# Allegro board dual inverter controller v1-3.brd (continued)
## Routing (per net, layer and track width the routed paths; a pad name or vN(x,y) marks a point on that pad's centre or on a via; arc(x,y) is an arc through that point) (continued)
Z-RTD-N-FILTER: length 5.4
  TOP w0.381: RT214.2 71.53,16.71 72.74,17.92 UT34.7
  TOP w0.508: RT214.2 CT142.2 70,16.62 LT23.2
Z-RTD-P: length 38.4
  TOP w0.381: JB6.9 34.42,8.62 37.03,11.23 54.06,11.23 61.11,18.27 66.78,18.27 LT20.1
Z-RTD-P-FILTER: length 5
  TOP w0.381: RT214.1 71.9,18.31 72.16,18.57 UT34.6
  TOP w0.508: RT214.1 CT142.1 70,18.4 LT20.2
Z-TEMP: length 22
  TOP w0.381: v1(101.64,44.39) 101.62,44.41 JT26.39
  BOTTOM w0.381: v1(101.64,44.39) 101.64,45.02 102.74,46.11 102.74,53.55 102.39,53.9 102.39,55.38 100.86,56.9 CB53.1 RB71.2
ZHS-PWM: length 46
  TOP w0.381: JT26.61 113.64,44.09 110.43,40.88 v1(104.91,40.88) 89.42,40.88 88.78,40.24 84.21,40.24 83.02,39.05 JT32.1
  TOP w0.508: RT165.1 77.98,34.09 80.71,36.81 JT32.1
ZHS-PWM-N: length 60.9
  TOP w0.381: JB6.4 28.06,5.49 28.06,11.75 30.36,14.04 51.18,14.04 66.54,29.4 71.12,29.4 71.64,29.92 73.27,29.92 UT26.3
ZHS-PWM-P: length 59
  TOP w0.381: JB6.3 26.8,11.28 30.12,14.6 50.95,14.6 66.3,29.95 70.89,29.95 71.41,30.48 73.3,30.48 UT26.2
ZLS-PWM: length 53.3
  TOP w0.381: JT26.63 114.43,43.76 110.76,40.09 v1(104.91,40.09) 89.74,40.09 89.12,39.46 JT33.1
  TOP w0.508: RT195.1 75.53,23.68 77.1,25.26 80.66,25.26 89.12,33.72 JT33.1
ZLS-PWM-N: length 58.6
  TOP w0.381: v1(29.22,10.02) 32.66,13.46 52.22,13.46 67.23,28.47 72.48,28.47 72.51,28.5 73.27,28.5 UT26.5
  BOTTOM w0.381: v1(29.22,10.02) 28.09,8.88 28.09,5.49 JB6.6
ZLS-PWM-P: length 54.3
  TOP w0.381: UT26.6 73.3,27.94 72.74,27.94 72.71,27.91 67.46,27.91 52.45,12.9 32.9,12.9 29.89,9.9 29.89,9.74 29.78,9.62 29.78,9.38 29.34,8.95 JB6.5
N07282: length 3.2
  TOP w0.381: UT8.4 98.74,115.56 v1(98.56,115.38)
  BOTTOM w0.381: v1(98.56,115.38) 98.56,114.29 RB13.2
N07299: length 3.6
  TOP w0.381: UT8.12 96.6,116.21 v1(96.78,116.39)
  BOTTOM w0.381: v1(96.78,116.39) 96.78,117.77 RB5.1
N07508: length 3.2
  TOP w0.381: v1(76.18,116.57) 75.87,116.26 UT4.4
  BOTTOM w0.381: v1(76.18,116.57) 76.18,117.54 RB6.2
N07516: length 3.3
  TOP w0.381: v1(78.22,115.43) 78.4,115.61 UT4.12
  BOTTOM w0.381: RB14.1 77.93,115.14 v1(78.22,115.43)
N07693: length 3.2
  TOP w0.381: UT1.4 v1(98.77,125.77)
  BOTTOM w0.381: RB3.2 98.77,124.71 v1(98.77,125.77)
N07878: length 3.2
  TOP w0.381: UT2.4 76.05,126.29 v1(76.24,126.47)
  BOTTOM w0.381: RB2.2 76.24,127.66 v1(76.24,126.47)
N09835: length 3.4
  TOP w0.381: UT1.1 102.25,123.82 CT6.1 RT20.2
N10049: length 3.7
  TOP w0.381: RT3.2 CT4.1 101.51,127.72 UT1.7
N10085: length 3.5
  TOP w0.381: RT2.2 CT3.1 93.23,128.37 UT1.9
N10121: length 3.5
  TOP w0.381: UT1.15 93.37,124.47 CT5.1 RT13.2
N11382: length 3.5
  TOP w0.381: UT1.12 v1(96.88,126.42)
  BOTTOM w0.381: RB1.2 96.88,127.73 v1(96.88,126.42)
N11987: length 3.3
  TOP w0.381: UT2.12 78.32,125.64 v1(78.14,125.46)
  BOTTOM w0.381: RB4.2 78.14,124.28 v1(78.14,125.46)
N12714: length 3
  TOP w0.381: RT1.2 CT1.1 74.17,128.48 UT2.1
N12754: length 5.8
  TOP w0.381: RT28.2 CT14.1 73.37,122.28 72.93,122.72 72.93,123.99 73.28,124.34 UT2.7
N16187: length 25
  LAYER3 w0.381: v1(84.96,65.03) 84.96,80.08 v1(83.73,81.31)
  BOTTOM w0.381: CB24.2 v1(83.73,81.31) ; RB66.1 84.59,64.66 v1(84.96,65.03)
  BOTTOM w0.508: UB6.1 80.28,83.89 81.38,82.78 81.61,82.78 82.18,82.21 UB6.4 82.97,82.78 CB24.2
N16636: length 2.8
  BOTTOM w0.508: CB24.1 RB38.1 RB35.2
N16643: length 3.3
  BOTTOM w0.508: RB38.2 83.67,84.15 82.81,84.15 82.27,84.69 UB6.3 82.41,84.92 CB18.2
N18013: length 2.8
  BOTTOM w0.508: CB25.1 RB39.1 RB36.2
N18021: length 26.1
  LAYER3 w0.381: v1(89.47,64.96) 93.46,68.94 v1(93.46,80.86)
  BOTTOM w0.381: v1(93.46,80.86) 93.46,81.5 92.97,81.99 UB7.4 ; RB67.1 v1(89.47,64.96)
  BOTTOM w0.508: UB7.1 90.45,83.89 91.56,82.78 91.78,82.78 92.35,82.21 UB7.4 93.15,82.78 CB25.2
N18093: length 3.3
  BOTTOM w0.508: CB19.2 92.58,84.92 UB7.3 92.45,84.69 92.99,84.15 93.85,84.15 RB39.2
N18488: length 2.8
  BOTTOM w0.508: RB37.2 RB40.1 CB26.1
N18496: length 29.8
  LAYER3 w0.381: v1(91.1,64.96) 97.08,70.94 97.08,73.13 97.04,73.17 97.04,77.53 99.35,79.84 101.74,79.84 v1(102.42,80.53)
  BOTTOM w0.381: RB68.1 v1(91.1,64.96) ; UB8.4 102.42,81.88 v1(102.42,80.53)
  BOTTOM w0.508: CB26.2 103.32,82.78 UB8.4 102.53,82.21 101.96,82.78 101.73,82.78 100.63,83.89 UB8.1
N18568: length 3.3
  BOTTOM w0.508: CB20.2 102.76,84.92 UB8.3 102.62,84.69 103.16,84.15 104.02,84.15 RB40.2
N76078: length 10
  TOP w0.381: RT27.2 45.03,121.52 RT29.1
  TOP w0.508: CT15.2 RT27.2
  TOP w0.635: RT12.2 40.9,120.77 41.64,120.02 RT29.1
N76134: length 2
  TOP w0.508: UT3.3 46.36,120.02 RT29.2
N76224: length 67.8
  TOP w0.381: UT3.1 51.75,119.44 v1(52.72,118.47)
  TOP w0.508: UT3.1 48.84,118.41 48.48,118.05 46.54,118.05 45.86,118.73 CT17.2 RT36.2
  BOTTOM w0.381: RB65.1 64.7,105.47 52.72,117.46 v1(52.72,118.47)
N76236: length 2.3
  TOP w0.508: RT43.2 46.36,115.93 46.94,116.52 UT3.4
N76260: length 5.5
  TOP w0.508: CT17.1 RT36.1 RT43.1
  TOP w0.635: RT42.2 42.38,116.19 42.64,115.93 RT43.1
N78650: length 2.8
  BOTTOM w0.508: RB25.2 RB18.1 CB7.1
N78658: length 9.6
  BOTTOM w0.381: RB26.1 75.52,95.99 76.53,97 76.53,97.85 76.09,98.28 75.88,98.28 75.35,98.81 UB2.1
  BOTTOM w0.508: UB2.1 75.35,99.83 74.25,100.94 74.02,100.94 73.45,101.51 UB2.4 72.66,100.94 CB7.2
N78724: length 3.3
  BOTTOM w0.508: RB18.2 71.96,99.57 72.82,99.57 73.36,99.03 UB2.3 73.22,98.8 CB9.2
N79088: length 5.9
  BOTTOM w0.381: RB28.2 72.33,96.76 71.9,97.19 RB25.1 ; RB28.2 CB10.2 ; RB28.2 70.99,95.99 RB27.1
N88263: length 1.6
  TOP w0.381: RT192.2 DT7.1
N88433: length 1.6
  TOP w0.381: RT193.2 DT8.1
N93191: length 1.9
  TOP w0.381: DT4.1 RT152.2
N93195: length 1.9
  TOP w0.381: DT6.1 RT154.2
N93199: length 1.9
  TOP w0.381: DT5.1 RT153.2
N139937: length 1.8
  TOP w0.635: RT10.2 RT11.1
N139941: length 1.8
  TOP w0.635: RT11.2 RT12.1
N140053: length 1.8
  TOP w0.635: RT40.2 RT41.1
N140057: length 1.8
  TOP w0.635: RT41.2 RT42.1
N147166: length 30.2
  TOP w0.381: 222.02,13.15 QT2.2 ; QT2.2 223.04,14.2 ; QT2.2 222.02,14.2 ; QT2.2 222.53,13.15 ; QT2.2 223.05,13.67 ; QT2.2 222.53,14.2 ; QT2.2 222.01,13.67 ; QT2.2 223.04,13.15 ; 222.02,14.42 QT2.3 ; QT2.3 223.04,14.42 ; QT2.3 222.01,14.94 ; QT2.3 223.05,14.94 ; QT2.3 223.04,15.47 ; QT2.3 222.02,15.47 ; QT2.3 222.53,14.42 ; QT2.3 222.53,15.47 ; QT3.3 225.57,14.2 ; QT3.3 225.57,13.15 ; QT3.3 225.06,13.15 ; QT3.3 224.55,13.15 ; QT3.3 224.55,14.2 ; QT3.3 225.58,13.67 ; QT3.3 224.54,13.67 ; QT3.3 225.06,14.2 ; QT2.1 223.04,12.93 ; QT2.1 222.02,11.88 ; QT2.1 223.05,12.4 ; QT2.1 222.53,12.93 ; QT2.1 222.02,12.93 ; QT2.1 223.04,11.88 ; QT2.1 222.01,12.4 ; QT2.1 222.53,11.88 ; QT3.2 225.58,14.94 ; QT3.2 224.54,14.94 ; QT3.2 225.57,14.42 ; QT3.2 225.06,14.42 ; QT3.2 224.55,15.47 ; QT3.2 224.55,14.42 ; QT3.2 225.06,15.47 ; QT3.2 225.57,15.47 ; 224.55,15.69 QT3.1 ; QT3.1 225.06,16.74 ; QT3.1 225.58,16.21 ; QT3.1 225.57,15.69 ; QT3.1 225.06,15.69 ; QT3.1 225.57,16.74 ; QT3.1 224.54,16.21 ; QT3.1 224.55,16.74
N148075: length 18.1
  TOP w0.254: v1(223.44,7.69) 222.23,7.69 UT37.10 221.85,7.7 221.52,7.37 221.52,7.35 221.41,7.23 RT222.2
  TOP w0.635: QT2.4 v1(222.53,17.78) ; v1(223.99,10.81) 224.43,10.81 225.06,11.45 QT3.4
  LAYER3 w0.635: v1(222.53,17.78) 222.53,12.27 v1(223.99,10.81) 223.44,10.26 v1(223.44,7.69)
N148197: length 1.4
  TOP w0.254: RT222.1 CT149.1
N148540: length 37.1
  TOP w0.178: 217.06,15.45 QT2.6 217.55,14.94 ; 217.06,14.18 QT2.7 217.55,13.67 ; 217.06,15.71 217.06,15.66 ; 217.06,12.91 QT2.8 217.55,12.4 ; 217.06,13.17 217.06,13.12 ; 217.55,16.21 QT2.5 ; 217.06,14.44 217.06,14.39
  TOP w0.254: 217.95,9.44 217.94,9.43 217.94,9.03 218.76,8.21 UT37.9
  TOP w0.381: QT2.5 217.06,16.74 ; QT2.5 217.57,15.69 ; QT2.5 217.57,16.74 ; QT2.5 216.55,15.69 ; QT2.5 216.55,16.74 ; QT2.5 216.54,16.21 ; QT2.6 217.57,15.47 ; QT2.6 217.57,14.42 ; QT2.6 216.55,14.42 ; QT2.6 216.54,14.94 ; QT2.6 216.55,15.47 ; QT2.7 217.57,14.2 ; QT2.7 217.57,13.15 ; QT2.7 216.55,13.15 ; QT2.7 216.54,13.67 ; QT2.7 216.55,14.2 ; RT220.1 220.11,11.12 ; RT220.1 220.11,9.72 ; RT220.1 216.31,11.12 ; RT220.1 220.11,10.42 ; RT220.1 216.31,9.72 ; RT220.1 218.21,11.24 ; RT220.1 218.21,9.59 ; RT220.1 216.31,10.42 ; QT2.8 217.57,12.93 ; QT2.8 216.54,12.4 ; QT2.8 217.57,11.88 ; QT2.8 216.55,12.93 ; QT2.8 216.55,11.88 ; QT2.8 217.06,11.88
N149103: length 13.2
  TOP w0.254: UT37.6 224.75,9.74 226.15,11.13 226.65,11.13 226.91,10.88 v1(227.8,10.88)
  TOP w0.381: RT218.1 RT217.2 231.86,10.24 v1(231.99,10.37)
  LAYER3 w0.254: v1(227.8,10.88) 228.31,10.37 v1(231.99,10.37)
N149107: length 4.1
  TOP w0.254: RT219.1 228.81,7.7 228.31,8.21 UT37.2
  TOP w0.381: RT218.2 RT219.1
N149113: length 8.6
  TOP w0.254: UT37.3 227.67,8.72 v1(227.92,8.97)
  TOP w0.381: RT221.1 RT219.2 231.01,7.96 v1(231.99,7.96)
  LAYER3 w0.254: v1(227.92,8.97) 229.55,8.97 230.57,7.96 v1(231.99,7.96)
N149983: length 4.6
  TOP w0.254: UT37.4 225.89,9.23 225.26,8.59 225.26,7.32 226.52,6.06 CT148.1
N150621: length 4.4
  TOP w0.254: UT37.7 223.1,9.23 224.62,7.7 RT223.2
N273504: length 4.3
  BOTTOM w0.254: UB3.5 82.43,88.96 83.31,88.08 RB32.2
  BOTTOM w0.508: RB35.1 83.73,86.4 83.31,86.82 RB32.2
N273798: length 3.1
  BOTTOM w0.254: CB15.2 80.81,87.81 81.67,88.68 81.67,89.65 81.88,89.86 UB3.6
N273802: length 3.3
  BOTTOM w0.254: CB15.1 RB29.2 81.04,90.62 81.54,90.62 81.8,90.37 UB3.7
N275299: length 4.3
  BOTTOM w0.254: UB4.5 92.61,88.96 93.49,88.08 RB33.2
  BOTTOM w0.508: RB36.1 93.91,86.4 93.49,86.82 RB33.2
N275399: length 3.3
  BOTTOM w0.254: CB16.1 RB30.2 91.22,90.62 91.72,90.62 91.97,90.37 UB4.7
N275407: length 3.1
  BOTTOM w0.254: UB4.6 92.06,89.86 91.84,89.65 91.84,88.68 90.98,87.81 CB16.2
N275841: length 4.3
  BOTTOM w0.254: UB5.5 102.78,88.96 103.66,88.08 RB34.2
  BOTTOM w0.508: RB34.2 103.66,86.82 104.08,86.4 RB37.1
N275941: length 3.3
  BOTTOM w0.254: CB17.1 RB31.2 101.39,90.62 101.89,90.62 102.15,90.37 UB5.7
N275949: length 3.1
  BOTTOM w0.254: CB17.2 101.16,87.81 102.02,88.68 102.02,89.65 102.23,89.86 UB5.6
N353091: length 3.2
  TOP w0.381: v1(98.64,18.98) 98.82,19.16 UT35.4
  BOTTOM w0.381: RB111.2 98.64,17.89 v1(98.64,18.98)
N353097: length 3.6
  TOP w0.381: UT35.12 96.68,19.81 v1(96.86,19.99)
  BOTTOM w0.381: RB109.1 96.86,21.37 v1(96.86,19.99)
N353101: length 3.2
  TOP w0.381: UT34.4 75.11,19.87 v1(75.42,20.18)
  BOTTOM w0.381: v1(75.42,20.18) 75.42,21.15 RB110.2
N353105: length 3.3
  TOP w0.381: UT34.12 77.63,19.22 v1(77.45,19.03)
  BOTTOM w0.381: v1(77.45,19.03) 77.16,18.74 RB112.1
N353111: length 3.2
  TOP w0.381: UT25.4 v1(98.79,28.61)
  BOTTOM w0.381: RB95.2 98.79,27.56 v1(98.79,28.61)
N353117: length 3.2
  TOP w0.381: v1(75.16,29.39) 74.98,29.21 UT26.4
  BOTTOM w0.381: v1(75.16,29.39) 75.16,30.57 RB91.2
N353179: length 3.4
  TOP w0.381: RT190.2 CT124.1 102.28,26.66 UT25.1
N353185: length 3.7
  TOP w0.381: RT168.2 CT110.1 101.53,30.56 UT25.7
N353187: length 3.5
  TOP w0.381: UT25.9 93.25,31.21 CT109.1 RT167.2
N353189: length 3.5
  TOP w0.381: UT25.15 93.39,27.31 CT120.1 RT185.2
N353203: length 3.5
  TOP w0.381: UT25.12 v1(96.9,29.26)
  BOTTOM w0.381: v1(96.9,29.26) 96.9,30.57 RB90.2
N353215: length 3.3
  TOP w0.381: UT26.12 77.25,28.56 v1(77.07,28.38)
  BOTTOM w0.381: v1(77.07,28.38) 77.07,27.2 RB96.2
N353221: length 3
  TOP w0.381: UT26.1 73.09,31.4 CT107.1 RT165.2
N353229: length 5.8
  TOP w0.381: UT26.7 72.21,27.26 71.86,26.91 71.86,25.64 72.3,25.2 CT127.1 RT195.2
N368949: length 4.3
  BOTTOM w0.254: RB50.2 83.31,73.82 82.43,74.69 UB9.5
  BOTTOM w0.508: RB50.2 83.31,72.55 83.73,72.13 RB53.1
N368957: length 2.8
  BOTTOM w0.508: RB53.2 RB56.1 CB40.1
N368965: length 19
  BOTTOM w0.381: CB40.2 83.73,67.7 84.11,67.32 87.28,67.32 88.71,65.9 93.22,65.9 94.35,64.76 RB69.1
  BOTTOM w0.508: UB12.1 80.28,69.63 81.38,68.52 81.61,68.52 82.18,67.95 UB12.4 82.97,68.52 CB40.2
N369195: length 3.3
  BOTTOM w0.508: CB33.2 82.41,70.66 UB12.3 82.27,70.43 82.81,69.88 83.67,69.88 RB56.2
N369283: length 3.3
  BOTTOM w0.254: CB30.1 RB47.2 81.04,76.36 81.54,76.36 81.8,76.11 UB9.7
N369291: length 3.1
  BOTTOM w0.254: UB9.6 81.88,75.6 81.67,75.39 81.67,74.42 80.81,73.55 CB30.2
N369511: length 2.8
  BOTTOM w0.508: RB54.2 RB57.1 CB41.1
N369519: length 13.6
  BOTTOM w0.381: UB13.4 92.1,67.5 93.12,66.48 96.53,66.48 97.61,65.4 RB70.1
  BOTTOM w0.508: CB41.2 92.89,68.52 UB13.4 92.1,67.95 91.53,68.52 91.3,68.52 90.2,69.63 UB13.1
N369535: length 4.3
  BOTTOM w0.254: UB10.5 92.35,74.69 93.23,73.82 RB51.2
  BOTTOM w0.508: RB54.1 93.65,72.13 93.23,72.55 RB51.2
N369765: length 3.3
  BOTTOM w0.508: CB34.2 92.33,70.66 UB13.3 92.19,70.43 92.73,69.88 93.59,69.88 RB57.2
N369853: length 3.3
  BOTTOM w0.254: UB10.7 91.72,76.11 91.46,76.36 90.96,76.36 RB48.2 CB31.1
N369861: length 3.1
  BOTTOM w0.254: CB31.2 90.73,73.55 91.59,74.42 91.59,75.39 91.8,75.6 UB10.6
N370089: length 4.3
  BOTTOM w0.254: UB11.5 102.27,74.69 103.15,73.82 RB52.2
  BOTTOM w0.508: RB52.2 103.15,72.55 103.57,72.13 RB55.1
N370097: length 2.8
  BOTTOM w0.508: CB42.1 RB58.1 RB55.2
N370105: length 9.5
  BOTTOM w0.381: RB71.1 102.49,66.31 102.02,66.78 UB14.4
  BOTTOM w0.508: CB42.2 102.81,68.52 UB14.4 102.02,67.95 101.45,68.52 101.22,68.52 100.12,69.63 UB14.1
N370335: length 3.3
  BOTTOM w0.508: RB58.2 103.51,69.88 102.65,69.88 102.11,70.43 UB14.3 102.25,70.66 CB35.2
N370423: length 3.3
  BOTTOM w0.254: CB32.1 RB49.2 100.88,76.36 101.38,76.36 101.64,76.11 UB11.7
N370431: length 3.1
  BOTTOM w0.254: CB32.2 100.65,73.55 101.51,74.42 101.51,75.39 101.72,75.6 UB11.6
N4877770: length 3
  TOP w0.381: RT14.2 RT21.1 125.7,121.65 CT8.1
N4877774: length 3
  TOP w0.381: CT9.2 133.25,121.65 RT22.1 RT15.2
N4883221: length 4.7
  TOP w0.381: UT5.5 131.38,118.57 130.2,119.76 RT22.2
N4883225: length 6.2
  TOP w0.381: UT5.6 UT5.7 133.82,119.89 v1(134.17,120.25)
  BOTTOM w0.381: RB8.1 132.52,118.6 v1(134.17,120.25)
N4883237: length 4.7
  TOP w0.381: UT5.10 127.57,118.57 128.75,119.76 RT21.2
N4883249: length 3.2
  TOP w0.381: UT5.8 UT5.9 125.28,119.23 125.23,119.18 125.07,119.18 124.52,118.64 RT33.1
N4883601: length 5.6
  TOP w0.381: CT28.1 RT44.1 124.72,115.69 124.52,115.89 RT33.2 125.31,116.66 125.37,116.59 UT5.13
N4883608: length 4.5
  TOP w0.381: UT5.14 126.32,115.83 RT44.2 CT28.2 RT50.1
N4883677: length 8.9
  TOP w0.381: UT5.12 127.65,117.25 v1(128.21,116.69)
  BOTTOM w0.381: v1(128.21,116.69) 128.21,116.57 128.39,116.38 128.39,116.04 128.86,115.57 129.4,115.57 ; 129.4,115.57 RB7.1 CB1.2 RB8.2 ; 129.4,115.57 129.18,115.35 129.18,114.41 RB15.2
N4893553: length 8.9
  TOP w0.381: UT6.12 139.81,117.25 v1(140.37,116.69)
  BOTTOM w0.381: 141.57,115.57 141.03,115.57 140.56,116.04 140.56,116.38 140.37,116.57 v1(140.37,116.69) ; 141.57,115.57 RB9.1 CB2.2 RB10.2 ; 141.57,115.57 141.35,115.35 141.35,114.41 RB16.2
N4893669: length 3
  TOP w0.381: CT11.2 145.42,121.65 RT24.1 RT17.2
N4893747: length 4.7
  TOP w0.381: RT24.2 142.37,119.76 143.55,118.57 UT6.5
N4893767: length 6.2
  TOP w0.381: UT6.6 UT6.7 145.99,119.89 v1(146.34,120.25)
  BOTTOM w0.381: RB10.1 144.69,118.6 v1(146.34,120.25)
N4893837: length 4.5
  TOP w0.381: UT6.14 138.49,115.83 RT45.2 CT29.2 RT51.1
N4893845: length 5.6
  TOP w0.381: CT29.1 RT45.1 136.89,115.69 136.69,115.89 RT34.2 137.48,116.66 137.54,116.59 UT6.13
N4893923: length 3
  TOP w0.381: CT10.1 137.87,121.65 RT23.1 RT16.2
N4893935: length 4.7
  TOP w0.381: UT6.10 139.74,118.57 140.92,119.76 RT23.2
N4893955: length 3.2
  TOP w0.381: RT34.1 136.69,118.64 137.24,119.18 137.4,119.18 137.45,119.23 UT6.9 UT6.8
N4894909: length 8.9
  TOP w0.381: UT7.12 151.98,117.25 v1(152.54,116.69)
  BOTTOM w0.381: RB12.2 CB3.2 RB11.1 153.74,115.57 ; RB17.2 153.52,114.41 153.52,115.35 153.74,115.57 ; 153.74,115.57 153.2,115.57 152.73,116.04 152.73,116.38 152.54,116.57 v1(152.54,116.69)
N4895025: length 3
  TOP w0.381: RT19.2 RT26.1 157.58,121.65 CT13.2
N4895103: length 4.7
  TOP w0.381: UT7.5 155.72,118.57 154.54,119.76 RT26.2
N4895123: length 6.2
  TOP w0.381: v1(158.51,120.25) 158.15,119.89 UT7.7 UT7.6
  BOTTOM w0.381: v1(158.51,120.25) 156.86,118.6 RB12.1
N4895193: length 4.5
  TOP w0.381: UT7.14 150.66,115.83 RT46.2 CT30.2 RT52.1
N4895201: length 5.6
  TOP w0.381: UT7.13 149.71,116.59 149.64,116.66 RT35.2 148.86,115.89 149.06,115.69 RT46.1 CT30.1
N4895279: length 3
  TOP w0.381: RT18.2 RT25.1 150.04,121.65 CT12.1
N4895291: length 4.7
  TOP w0.381: UT7.10 151.91,118.57 153.09,119.76 RT25.2
N4895311: length 3.2
  TOP w0.381: UT7.8 UT7.9 149.62,119.23 149.57,119.18 149.4,119.18 148.86,118.64 RT35.1
N4895784: length 3
  TOP w0.381: RT206.2 RT199.1 125.75,21.52 CT137.1
N4895786: length 3
  TOP w0.381: CT136.2 118.21,21.52 RT198.1 RT205.2
N4895800: length 4.7
  TOP w0.381: RT198.2 121.26,23.41 120.08,24.6 UT29.5
N4895802: length 6.2
  TOP w0.381: UT29.6 UT29.7 117.64,23.27 v1(117.28,22.92)
  BOTTOM w0.381: RB97.1 118.93,24.57 v1(117.28,22.92)
N4895808: length 4.7
  TOP w0.381: UT29.10 123.89,24.6 122.71,23.41 RT199.2
N4895810: length 3.2
  TOP w0.381: UT29.8 UT29.9 126.17,23.94 126.22,23.99 126.39,23.99 126.94,24.53 RT187.1
N4895816: length 5.6
  TOP w0.381: UT29.13 126.09,26.58 126.15,26.51 RT187.2 126.94,27.28 126.73,27.48 RT181.1 CT113.1
N4895820: length 4.5
  TOP w0.381: CT113.2 RT181.2 125.13,27.34 UT29.14
  TOP w0.508: CT113.2 125.08,30.17 RT169.1
N4895842: length 8.9
  TOP w0.381: v1(123.25,26.48) 123.81,25.92 UT29.12
  BOTTOM w0.381: 122.06,27.6 RB98.1 CB74.2 RB97.2 ; 122.06,27.6 122.59,27.6 123.07,27.13 123.07,26.79 123.25,26.6 v1(123.25,26.48) ; 122.06,27.6 122.27,27.82 122.27,28.76 RB92.2
N4895902: length 8.9
  TOP w0.381: v1(135.42,26.48) 135.98,25.92 UT30.12
  BOTTOM w0.381: 134.22,27.6 RB100.1 CB75.2 RB99.2 ; 134.22,27.6 134.76,27.6 135.23,27.13 135.23,26.79 135.42,26.6 v1(135.42,26.48) ; 134.22,27.6 134.44,27.82 134.44,28.76 RB93.2
N4895932: length 3
  TOP w0.381: RT207.2 RT200.1 130.38,21.52 CT138.2
N4895942: length 4.7
  TOP w0.381: RT200.2 133.43,23.41 132.25,24.6 UT30.5
N4895944: length 6.2
  TOP w0.381: UT30.6 UT30.7 129.81,23.27 v1(129.45,22.92)
  BOTTOM w0.381: RB99.1 131.1,24.57 v1(129.45,22.92)
N4895958: length 4.5
  TOP w0.381: CT114.2 RT182.2 137.3,27.34 UT30.14
  TOP w0.508: CT114.2 137.25,30.17 RT170.1
N4895962: length 5.6
  TOP w0.381: CT114.1 RT182.1 138.9,27.48 139.1,27.28 RT188.2 138.32,26.51 138.25,26.58 UT30.13
N4895972: length 3
  TOP w0.381: CT139.1 137.92,21.52 RT201.1 RT208.2
N4895978: length 4.7
  TOP w0.381: RT201.2 134.87,23.41 136.06,24.6 UT30.10
N4895980: length 3.2
  TOP w0.381: UT30.8 UT30.9 138.34,23.94 138.39,23.99 138.56,23.99 139.1,24.53 RT188.1
N4896016: length 8.9
  TOP w0.381: v1(147.59,26.48) 148.15,25.92 UT31.12
  BOTTOM w0.381: 146.39,27.6 146.93,27.6 147.4,27.13 147.4,26.79 147.59,26.6 v1(147.59,26.48) ; 146.39,27.6 146.61,27.82 146.61,28.76 RB94.2 ; 146.39,27.6 RB102.1 CB76.2 RB101.2
N4896046: length 3
  TOP w0.381: RT209.2 RT202.1 142.55,21.52 CT140.2
N4896056: length 4.7
  TOP w0.381: UT31.5 144.41,24.6 145.59,23.41 RT202.2
N4896058: length 6.2
  TOP w0.381: v1(141.62,22.92) 141.97,23.27 UT31.7 UT31.6
  BOTTOM w0.381: v1(141.62,22.92) 143.27,24.57 RB101.1
N4896072: length 4.5
  TOP w0.381: CT115.2 RT183.2 149.47,27.34 UT31.14
  TOP w0.508: CT115.2 149.42,30.17 RT171.1
N4896076: length 5.6
  TOP w0.381: UT31.13 150.42,26.58 150.49,26.51 RT189.2 151.27,27.28 151.07,27.48 RT183.1 CT115.1
N4896086: length 3
  TOP w0.381: CT141.1 150.09,21.52 RT203.1 RT210.2
N4896092: length 4.7
  TOP w0.381: UT31.10 148.22,24.6 147.04,23.41 RT203.2
N4896094: length 3.2
  TOP w0.381: UT31.8 UT31.9 150.51,23.94 150.56,23.99 150.73,23.99 151.27,24.53 RT189.1
N4909322: length 59.4
  TOP w0.381: RT78.2 195.81,85.73 195.79,85.75 JT15.1 171.94,86.83 v1(155.85,70.73)
  BOTTOM w0.381: UB17.1 157.69,63.76 155.85,65.6 v1(155.85,70.73)
N4927414: length 1.8
  BOTTOM w0.635: RB21.2 RB22.1
N4927416: length 1.8
  BOTTOM w0.635: RB22.2 RB23.1
N4927418: length 1.8
  BOTTOM w0.635: RB23.2 RB24.1
N4927420: length 1.8
  TOP w0.635: RT57.2 RT58.1
N4927422: length 1.8
  TOP w0.635: RT58.2 RT59.1
N4927424: length 1.8
  TOP w0.635: RT59.2 RT60.1
N4927426: length 7.6
  TOP w0.381: RT62.1 52.93,105.64 RT61.2
  TOP w0.508: CT34.2 RT61.2
  TOP w0.635: RT60.2 49.28,105.26 50.4,104.14 RT62.1
N4927452: length 1.8
  TOP w0.635: RT69.2 RT70.1
N4927454: length 1.8
  TOP w0.635: RT70.2 RT71.1
N4927456: length 1.8
  TOP w0.635: RT71.2 RT72.1
N4927458: length 7.5
  TOP w0.381: RT74.1 52.93,90.64 RT73.2
  TOP w0.508: CT39.2 RT73.2
  TOP w0.635: RT74.1 50.16,89.14 49.28,90.02 RT72.2
N4927466: length 1.8
  BOTTOM w0.635: RB43.2 RB44.1
N4927468: length 1.8
  BOTTOM w0.635: RB44.2 RB45.1
N4927470: length 1.8
  BOTTOM w0.635: RB45.2 RB46.1
N4927472: length 5.8
  TOP w0.508: CT41.1 RT76.1 RT77.1
  TOP w0.635: RT77.1 51.44,84.61 v1(50.56,83.73)
  BOTTOM w0.635: RB46.2 50.54,83.74 v1(50.56,83.73)
N4927476: length 1.8
  TOP w0.635: RT86.2 RT87.1
N4927478: length 1.8
  TOP w0.635: RT87.2 RT88.1
N4927480: length 1.8
  TOP w0.635: RT88.2 RT89.1
N4927482: length 7.1
  TOP w0.381: RT90.2 52.93,75.64 RT92.1
  TOP w0.508: CT47.2 RT90.2
  TOP w0.635: RT92.1 50.42,74.14 49.28,75.28 RT89.2
N4927490: length 1.8
  BOTTOM w0.635: RB61.2 RB62.1
N4927492: length 1.8
  BOTTOM w0.635: RB62.2 RB63.1
N4927494: length 1.8
  BOTTOM w0.635: RB63.2 RB64.1
N4927496: length 6.1
  TOP w0.508: CT50.1 RT94.1 RT97.1
  TOP w0.635: v1(50.63,68.5) 50.81,68.5 51.44,69.14 51.44,70.04 RT97.1
  BOTTOM w0.635: v1(50.63,68.5) RB64.2
N4927508: length 1.8
  TOP w0.635: RT55.2 RT56.1
N4927510: length 1.8
  BOTTOM w0.635: RB19.2 RB20.1
N4927512: length 1.8
  TOP w0.635: RT56.2 RT57.1
N4927514: length 1.8
  BOTTOM w0.635: RB20.2 RB21.1
N4927522: length 1.8
  TOP w0.635: RT67.2 RT68.1
N4927524: length 1.8
  TOP w0.635: RT68.2 RT69.1
N4927528: length 1.8
  BOTTOM w0.635: RB41.2 RB42.1
N4927530: length 1.8
  BOTTOM w0.635: RB42.2 RB43.1
N4927534: length 1.8
  TOP w0.635: RT84.2 RT85.1
N4927536: length 1.8
  TOP w0.635: RT85.2 RT86.1
N4927540: length 1.8
  BOTTOM w0.635: RB59.2 RB60.1
N4927542: length 1.8
  BOTTOM w0.635: RB60.2 RB61.1
N4927556: length 55.2
  TOP w0.381: v1(58.68,104.5) 57.74,103.56 UT10.1
  TOP w0.508: RT64.2 CT35.2 53.89,102.84 54.52,102.22 56.31,102.22 56.74,102.65 UT10.1
  BOTTOM w0.381: RB72.1 63.94,61.58 63.38,62.13 63.38,100.82 59.7,104.5 v1(58.68,104.5)
N4927564: length 5.5
  TOP w0.508: CT35.1 RT64.1 RT65.1
  TOP w0.635: v1(50.43,98.94) 51.44,99.94 RT65.1
  BOTTOM w0.635: RB24.2 50.39,98.98 v1(50.43,98.94)
N4927568: length 2.1
  TOP w0.508: UT10.4 54.78,100.86 53.97,100.05 RT65.2
N4927572: length 2
  TOP w0.508: UT10.3 54.55,103.56 53.97,104.14 RT62.2
N4927618: length 2
  TOP w0.508: UT11.3 54.55,88.56 53.97,89.14 RT74.2
N4927622: length 45.1
  TOP w0.381: UT11.1 57.36,88.56 v1(58.68,89.88)
  TOP w0.508: UT11.1 56.74,87.65 56.31,87.22 54.52,87.22 53.89,87.84 CT41.2 RT76.2
  BOTTOM w0.381: RB73.1 63.94,56.62 62.37,58.19 62.37,86.2 v1(58.68,89.88)
N4927628: length 2.1
  TOP w0.508: UT11.4 54.78,85.86 53.97,85.05 RT77.2
N4927670: length 2
  TOP w0.508: UT14.3 54.55,73.56 53.97,74.14 RT92.2
N4927674: length 35
  TOP w0.381: UT14.1 57.58,73.56 v1(58.81,74.79)
  TOP w0.508: UT14.1 56.74,72.65 56.31,72.22 54.52,72.22 53.89,72.84 CT50.2 RT94.2
  BOTTOM w0.381: v1(58.81,74.79) 58.81,70.21 61.61,67.42 61.61,54 63.94,51.67 RB80.1
N4927680: length 2.1
  TOP w0.508: UT14.4 54.78,70.86 53.97,70.05 RT97.2
N4932848: length 1.8
  BOTTOM w0.635: RB76.2 RB77.1
N4932850: length 1.8
  BOTTOM w0.635: RB77.2 RB78.1
N4932852: length 1.8
  BOTTOM w0.635: RB78.2 RB79.1
N4932854: length 1.8
  TOP w0.635: RT108.2 RT109.1
N4932856: length 1.8
  TOP w0.635: RT109.2 RT110.1
N4932858: length 1.8
  TOP w0.635: RT110.2 RT111.1
N4932860: length 6.9
  TOP w0.381: RT114.1 52.93,60.64 RT112.2
  TOP w0.508: CT65.2 RT112.2
  TOP w0.635: RT114.1 50.42,59.14 49.28,60.28 RT111.2
N4932886: length 1.8
  TOP w0.635: RT132.2 RT133.1
N4932888: length 1.8
  TOP w0.635: RT133.2 RT134.1
N4932890: length 1.8
  TOP w0.635: RT134.2 RT135.1
N4932892: length 6.7
  TOP w0.381: RT137.1 52.93,45.64 RT136.2
  TOP w0.508: CT81.2 RT136.2
  TOP w0.635: RT135.2 49.28,45.28 50.42,44.14 RT137.1
N4932900: length 1.8
  BOTTOM w0.635: RB85.2 RB86.1
N4932902: length 1.8
  BOTTOM w0.635: RB86.2 RB87.1
N4932904: length 1.8
  BOTTOM w0.635: RB87.2 RB88.1
N4932906: length 6.6
  TOP w0.508: RT142.1 RT141.1 CT86.1
  TOP w0.635: RT142.1 51.44,38.66 50.8,38.02 v1(50.56,38.02)
  BOTTOM w0.635: RB88.2 v1(50.56,38.02)
N4932910: length 1.8
  TOP w0.635: RT176.2 RT177.1
N4932912: length 1.8
  TOP w0.635: RT177.2 RT178.1
N4932914: length 1.8
  TOP w0.635: RT178.2 RT179.1
N4932916: length 6.4
  TOP w0.381: RT180.1 52.93,30.64 RT173.2
  TOP w0.508: CT112.2 RT173.2
  TOP w0.635: RT180.1 50.42,29.14 49.28,30.28 RT179.2
N4932924: length 1.8
  BOTTOM w0.635: RB105.2 RB106.1
N4932926: length 1.8
  BOTTOM w0.635: RB106.2 RB107.1
N4932928: length 1.8
  BOTTOM w0.635: RB107.2 RB108.1
N4932930: length 6.7
  TOP w0.508: CT117.1 RT184.1 RT191.1
  TOP w0.635: RT191.1 51.44,25.04 51.44,23.73 v1(50.56,22.84)
  BOTTOM w0.635: RB108.2 50.5,22.78 v1(50.56,22.84)
N4932934: length 1.8
  TOP w0.635: RT106.2 RT107.1
N4932936: length 1.8
  BOTTOM w0.635: RB74.2 RB75.1
N4932938: length 1.8
  TOP w0.635: RT107.2 RT108.1
N4932940: length 1.8
  BOTTOM w0.635: RB75.2 RB76.1
N4932948: length 1.8
  TOP w0.635: RT130.2 RT131.1
N4932950: length 1.8
  TOP w0.635: RT131.2 RT132.1
N4932954: length 1.8
  BOTTOM w0.635: RB83.2 RB84.1
N4932956: length 1.8
  BOTTOM w0.635: RB84.2 RB85.1
N4932960: length 1.8
  TOP w0.635: RT174.2 RT175.1
N4932962: length 1.8
  TOP w0.635: RT175.2 RT176.1
N4932966: length 1.8
  BOTTOM w0.635: RB103.2 RB104.1
N4932968: length 1.8
  BOTTOM w0.635: RB104.2 RB105.1
N4932978: length 24.5
  TOP w0.381: v1(58.56,59.55) 57.57,58.56 UT18.1
  TOP w0.508: UT18.1 56.74,57.65 56.31,57.22 54.52,57.22 53.89,57.84 CT68.2 RT116.2
  BOTTOM w0.381: RB81.1 63.94,46.72 58.56,52.1 v1(58.56,59.55)
N4932986: length 6.4
  TOP w0.508: RT118.1 RT116.1 CT68.1
  TOP w0.635: RT118.1 51.44,53.86 50.8,53.22 v1(50.51,53.22)
  BOTTOM w0.635: v1(50.51,53.22) 50.46,53.26 RB79.2
N4932990: length 2.1
  TOP w0.508: RT118.2 53.97,55.05 54.78,55.86 UT18.4
N4932994: length 2
  TOP w0.508: RT114.2 53.97,59.14 54.55,58.56 UT18.3
N4933040: length 2
  TOP w0.508: RT137.2 53.97,44.14 54.55,43.56 UT21.3
N4933044: length 15.2
  TOP w0.381: v1(60.59,42.91) 59.94,43.56 UT21.1
  TOP w0.508: UT21.1 56.74,42.65 56.31,42.22 54.52,42.22 53.89,42.84 CT86.2 RT141.2
  BOTTOM w0.381: v1(60.59,42.91) 61.73,41.77 RB82.1
N4933050: length 2.1
  TOP w0.508: RT142.2 53.97,40.05 54.78,40.86 UT21.4
N4933092: length 2
  TOP w0.508: RT180.2 53.97,29.14 54.55,28.56 UT32.3
N4933096: length 18.8
  TOP w0.381: v1(58.56,29.76) 57.36,28.56 UT32.1
  TOP w0.508: UT32.1 56.74,27.65 56.31,27.22 54.52,27.22 53.89,27.84 CT117.2 RT184.2
  BOTTOM w0.381: RB89.1 63.94,36.81 58.56,31.43 v1(58.56,29.76)
N4933102: length 2.1
  TOP w0.508: UT32.4 54.78,25.86 53.97,25.05 RT191.2
N5087389: length 1.8
  TOP w0.635: RT7.2 RT8.1
N5087393: length 1.8
  TOP w0.635: RT8.2 RT9.1
N5087445: length 1.8
  TOP w0.635: RT37.2 RT38.1
N5087449: length 1.8
  TOP w0.635: RT38.2 RT39.1
N5087463: length 1.8
  TOP w0.635: RT9.2 RT10.1
N5087477: length 1.8
  TOP w0.635: RT39.2 RT40.1
N5215633: length 6.5
  TOP w0.127: RT81.2 204.07,77.54 ; 205.58,76.03 CT49.2
  TOP w0.381: 205.58,76.03 204.97,76.64 204.97,76.66 204.76,76.88 204.74,76.88 204.07,77.54
  TOP w0.508: UT13.3 202.43,76.84 203.18,77.59 RT81.2 ; CT49.2 RT91.1
N5215739: length 4.9
  TOP w0.508: RT83.1 197.12,76.21 RT82.2 CT46.2 199.66,76.05 199.71,76 UT13.1
N5215763: length 7.6
  TOP w0.508: RT79.2 203.69,78.7 UT13.4 202.43,78.48 201.49,77.53 199.78,77.53 199.66,77.65 CT46.1 RT82.1
N5219233: length 1.7
  BOTTOM w0.508: UB16.5 213.24,65.73 CB47.1
N5220223: length 6.5
  TOP w0.127: 204.07,70.02 RT96.2
  TOP w0.381: CT57.2 204.69,69.44 204.66,69.44 204.07,70.02
  TOP w0.508: CT57.2 RT100.1 ; RT96.2 203.18,70.07 202.43,69.33 UT15.3
N5220393: length 4.9
  TOP w0.508: RT99.1 197.12,68.7 RT98.2 CT55.2 199.66,68.54 199.71,68.49 UT15.1
N5220405: length 7.6
  TOP w0.508: RT93.2 203.69,71.19 UT15.4 202.43,70.96 201.49,70.01 199.78,70.01 199.66,70.14 CT55.1 RT98.1
N5225791: length 1.7
  BOTTOM w0.508: UB1.1 147.87,105.29 CB6.1
N5226417: length 1.7
  BOTTOM w0.508: CB69.1 139.7,38.5 UB21.1
N5226863: length 1.7
  TOP w0.508: UT16.5 57.92,66.65 CT59.1
N5227646: length 6.5
  TOP w0.381: CT67.2 205.58,61 204.97,61.61 204.97,61.64 204.69,61.92 204.66,61.92 204.07,62.51 RT103.2
  TOP w0.508: UT17.3 202.43,61.81 203.18,62.56 RT103.2 ; RT113.1 CT67.2
N5227670: length 4.9
  TOP w0.508: RT105.1 197.12,61.18 RT104.2 CT64.2 199.66,61.02 199.71,60.97 UT17.1
N5227676: length 7.6
  TOP w0.508: RT101.2 203.69,63.67 UT17.4 202.43,63.44 201.49,62.5 199.78,62.5 199.66,62.62 CT64.1 RT104.1
N5227730: length 6.5
  TOP w0.381: RT119.2 204.07,54.99 204.66,54.41 204.69,54.41 204.97,54.12 204.97,54.1 205.58,53.49 CT75.2
  TOP w0.508: RT119.2 203.18,55.04 202.43,54.29 UT19.3 ; RT122.1 CT75.2
N5227754: length 4.9
  TOP w0.508: RT121.1 197.12,53.67 RT120.2 CT73.2 199.66,53.5 199.71,53.45 UT19.1
N5227760: length 7.6
  TOP w0.508: RT120.1 CT73.1 199.66,55.1 199.78,54.98 201.49,54.98 202.43,55.93 UT19.4 203.69,56.15 RT115.2
N5284170: length 4.7
  TOP w0.381: RT66.2 CT37.1 188.56,95.32 188.63,95.39 JT13.1
N5287176: length 4.8
  TOP w0.381: RT75.2 CT40.1 187.91,89.45 188.14,89.68 JT14.1
N5307958: length 15.9
  TOP w0.381: 233.48,45.25 LT13.2 ; LT13.2 233.6,43.04 ; LT13.2 235.26,43.04 ; LT13.2 234.43,43.04 ; LT13.2 235.38,45.25 ; 232.29,43.52 DT3.2 ; DT3.2 232.9,43.52 ; DT3.2 232.29,45.19 ; DT3.2 231.63,44.36 ; DT3.2 232.95,44.36 ; DT3.2 231.69,45.19 ; DT3.2 231.69,43.52 ; DT3.2 232.9,45.19
N5307974: length 34.1
  TOP w0.254: RT159.2 234.62,35.56 v1(234.45,35.72)
  TOP w0.381: QT1.3 227.41,46.37 ; QT1.3 226.9,46.37 ; QT1.3 227.42,46.9 ; QT1.3 226.38,46.9 ; QT1.3 226.39,46.37 ; 226.38,44.36 QT1.1 ; QT1.1 226.9,44.88 ; QT1.1 226.39,43.83 ; QT1.1 227.41,43.83 ; QT1.1 227.42,44.36 ; QT1.1 226.39,44.88 ; QT1.1 227.41,44.88 ; QT1.1 226.9,43.83 ; QT1.2 227.42,45.63 ; QT1.2 226.38,45.63 ; QT1.2 226.39,46.15 ; QT1.2 227.41,45.1 ; QT1.2 226.9,46.15 ; QT1.2 226.9,45.1 ; QT1.2 226.39,45.1 ; QT1.2 227.41,46.15 ; DT3.1 229.65,44.36 ; DT3.1 229.59,43.52 ; DT3.1 229.59,45.2 ; DT3.1 228.99,45.2 ; DT3.1 228.39,43.52 ; DT3.1 228.39,45.2 ; DT3.1 228.33,44.36 ; DT3.1 228.99,43.52
  LAYER3 w0.508: v1(234.45,35.72) 233.82,35.72 230.01,39.53 230.01,44.36 v1(228.61,45.75)
N5308194: length 20.9
  TOP w0.254: v1(236.36,39.53) 236.23,39.53 236.23,39.53 235.98,39.53 235.96,39.54 UT22.3
  TOP w0.381: RT124.2 229.95,48.46 ; RT124.2 229.95,49.09 ; RT124.2 229.25,49.11 ; RT124.2 228.54,48.46 ; RT124.2 228.54,49.09 ; QT1.4 227.42,48.17 ; QT1.4 227.41,48.69 ; QT1.4 226.38,48.17 ; QT1.4 226.39,48.69 ; QT1.4 226.9,48.69
  LAYER3 w0.508: v1(227.97,48.04) 228.48,47.53 230.13,47.53 236.36,41.31 v1(236.36,39.53)
N5308460: length 9
  TOP w0.254: UT22.13 230.42,40.04 229.67,40.79 226.66,40.79 RT147.1 RT146.1
  TOP w0.381: UT24.3 223.38,39.83 223.66,40.1 RT146.1
N5308524: length 2.3
  TOP w0.254: UT22.4 235.98,40.04 236.07,40.14 236.77,40.14 237.02,39.89 237.23,39.89 RT145.2
N5308658: length 3.7
  TOP w0.254: RT155.1 236.7,38.3 235.96,39.04 UT22.2
  TOP w0.381: RT155.1 CT98.2
N5308830: length 1.4
  TOP w0.508: RT155.2 237.37,35.5 CT104.1
N5309781: length 6.3
  TOP w0.381: CT100.1 RT161.2 222.97,37.52 222.66,37.83 222.66,38.48 222.07,39.08 221.65,39.08 221.38,39.35 UT24.1
N5377291: length 2.6
  TOP w0.381: RT228.1 215.24,95.56 UT38.12
N5387179: length 8.6
  TOP w0.381: UT38.18 214.26,103.18 v1(214.67,102.78) 215.08,102.78 CT152.2 215.57,103.26 LT27.1 ; UT38.20 214.17,106.33 v1(214.31,106.33)
  BOTTOM w0.381: v1(214.31,106.33) 214.67,105.98 v1(214.67,102.78)
N5387193: length 3.7
  TOP w0.381: LT26.1 216.98,104.82 CT152.1 215.16,104.45 UT38.19
N5390614: length 2.6
  TOP w0.381: RT227.1 202.95,95.38 203.13,95.56 UT38.9
N5390858: length 2.6
  TOP w0.381: RT226.1 203.08,96.88 203.13,96.83 UT38.8
N5390867: length 2.6
  TOP w0.381: RT225.1 203.06,99.3 203.13,99.37 UT38.6
N5429427: length 1.8
  TOP w0.254: UT41.3 207.74,38.16 207.72,38.18 RT229.1
N5429751: length 11.9
  TOP w0.254: RT247.2 207.74,39.55 207.83,39.46 UT41.1 208.82,40.1 209.33,40.61 215.71,40.61 215.72,40.62 RT230.1 CT157.1
N5430286: length 9.3
  TOP w0.254: v1(207.15,37.04) 207.43,37.04 207.79,37.4 207.92,37.4 208.03,37.51 UT41.4 209.61,37.51 209.91,37.81 209.91,38.64 209.73,38.82 208.83,38.82 UT41.2
  BOTTOM w0.381: RB114.2 RB116.1 CB79.1 207.34,37.23 v1(207.15,37.04)
N5430623: length 13.8
  TOP w0.254: CT158.1 RT233.1 208.64,34.4 207.91,35.13 207.84,35.13 207.12,35.85 RT249.2 207.03,35.94 207.28,36.19 207.46,36.19 208.13,36.86 UT41.5
N5431331: length 1.4
  TOP w0.254: CT169.1 RT247.1
N5431438: length 1.4
  TOP w0.254: RT249.1 CT170.1
N5432011: length 7.2
  TOP w0.381: RT164.1 198.36,41.9 RT236.1 195.33,41.9 193.52,43.71 CT103.2 RT163.2
N5433071: length 1.7
  TOP w0.254: QT5.3 201.99,38.74 RT248.2
N5433075: length 5.7
  TOP w0.254: RT248.1 RT235.2 203.59,40.91 204.42,41.74 206.23,41.74 207.01,40.95 CT169.2
N5433096: length 5.7
  TOP w0.254: QT5.2 203.59,35.8 RT234.1 203.59,34.44 204.38,33.66 206.23,33.66 207.03,34.45 CT170.2
N5433357: length 7
  TOP w0.381: RT164.2 CT159.2 200.05,38.86 UT39.1 199.94,38.53 200.47,38.01 200.91,38.01 201.85,37.07 QT5.1
N5434399: length 6.2
  TOP w0.381: UT39.4 198.04,36.28 196.97,37.36 RT236.2 196.98,40.31 CT159.1
N5434918: length 7.4
  TOP w0.381: UT39.3 v1(198.04,37.75)
  BOTTOM w0.381: RB113.2 203.31,35.93 RB115.1 CB83.1 199.24,35.93 198.04,37.13 198.04,37.74 v1(198.04,37.75)
N5437148: length 11.9
  TOP w0.254: RT250.2 207.94,48.22 208.04,48.12 UT43.1 209.02,48.77 209.53,49.28 215.92,49.28 215.93,49.29 RT237.1 CT162.1
N5437220: length 5.7
  TOP w0.254: RT251.1 RT239.2 203.79,49.58 204.62,50.4 206.43,50.4 207.22,49.62 CT167.2
N5437228: length 1.4
  TOP w0.254: CT167.1 RT250.1
N5437378: length 1.8
  TOP w0.254: UT43.3 207.94,46.82 207.92,46.85 RT238.1
N5437474: length 9.5
  TOP w0.254: v1(207.36,45.71) 207.63,45.71 207.99,46.07 208.12,46.07 208.23,46.17 UT43.4 209.82,46.17 210.12,46.47 210.12,47.31 209.94,47.49 209.03,47.49 UT43.2
  BOTTOM w0.381: v1(207.36,45.71) 207.36,46.33 207.34,46.35 CB81.1 RB120.1 RB117.2
N5437598: length 13.8
  TOP w0.254: CT166.1 RT244.1 208.84,43.07 208.11,43.79 208.04,43.79 207.32,44.52 RT252.2 207.23,44.6 207.48,44.86 207.66,44.86 208.33,45.52 UT43.5
N5437614: length 1.7
  TOP w0.254: QT4.3 202.19,47.41 RT251.2
N5437712: length 7.3
  TOP w0.381: UT40.3 v1(198.04,46.72)
  BOTTOM w0.381: RB118.2 203.2,44.79 RB119.1 CB84.1 199.36,44.79 198.04,46.1 v1(198.04,46.72)
N5437790: length 7.4
  TOP w0.381: RT246.2 CT165.2 200.05,47.78 UT40.1 199.94,47.45 200.53,46.87 201.07,46.87 202.05,45.89 QT4.1
N5437806: length 6.5
  TOP w0.381: RT246.1 197,50.73 RT243.1 196.13,50.78 196.08,50.74 RT242.2 CT164.2
N5437826: length 6.2
  TOP w0.381: UT40.4 198.04,45.2 196.94,46.3 RT243.2 196.99,49.23 CT165.1
N5437838: length 5.7
  TOP w0.254: QT4.2 203.79,44.47 RT245.1 203.79,43.11 204.58,42.32 206.43,42.32 207.23,43.12 CT168.2
N5437898: length 1.4
  TOP w0.254: RT252.1 CT168.1

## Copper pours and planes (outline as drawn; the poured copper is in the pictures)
+3V3 on PWR: 234,144.49 240.71,141.71 243.49,135 243.49,122.33 243.06,121.27 242,120.84 206.63,120.84 205.58,120.4 205.14,119.34 205.14,81.61 205.58,80.56 206.63,80.12 242,80.12 243.06,79.68 243.49,78.63 243.49,10 240.71,3.29 234,0.51 126,0.51 124.94,0.94 124.51,2 124.51,4.5 120,9.01 115.49,4.5 115.49,2 115.06,0.94 114,0.51 20.68,0.51 19.62,0.94 19.19,2 19.19,5.15 19.46,6.52 20.24,7.69 27.35,14.8 28.52,15.58 29.9,15.86 47.16,15.86 48.21,16.29 48.65,17.35 48.65,106.43 48.54,107 48.21,107.48 40.71,114.99 40.38,115.47 40.27,116.04 40.27,129.1 39.83,130.15 38.78,130.59 29.9,130.59 28.52,130.86 27.35,131.64 20.24,138.76 19.46,139.92 19.19,141.3 19.19,143 19.62,144.06 20.68,144.49 114,144.49 115.06,144.06 115.49,143 115.49,140.5 120,135.99 124.51,140.5 124.51,143 124.94,144.06 126,144.49
+5V on PWR2: 234,144.49 240.71,141.71 243.49,135 243.49,122.33 243.06,121.27 242,120.84 206.63,120.84 205.58,120.4 205.14,119.34 205.14,81.61 205.58,80.56 206.63,80.12 242,80.12 243.06,79.68 243.49,78.63 243.49,10 240.71,3.29 234,0.51 126,0.51 124.94,0.94 124.51,2 124.51,4.5 120,9.01 115.49,4.5 115.49,2 115.06,0.94 114,0.51 20.68,0.51 19.62,0.94 19.19,2 19.19,5.15 19.46,6.52 20.24,7.69 27.35,14.8 28.52,15.58 29.9,15.86 47.16,15.86 48.21,16.29 48.65,17.35 48.65,106.43 48.54,107 48.21,107.48 40.71,114.99 40.38,115.47 40.27,116.04 40.27,129.1 39.83,130.15 38.78,130.59 29.9,130.59 28.52,130.86 27.35,131.64 20.24,138.76 19.46,139.92 19.19,141.3 19.19,143 19.62,144.06 20.68,144.49 114,144.49 115.06,144.06 115.49,143 115.49,140.5 120,135.99 124.51,140.5 124.51,143 124.94,144.06 126,144.49
+5V-ISO on PWR: 233.85,115.41 234.75,115.04 235.12,114.14 235.12,85.87 234.75,84.97 233.85,84.6 214,84.6 213.11,84.97 212.74,85.87 212.74,100.9 213.11,101.8 214,102.17 218.65,102.17 219.1,102.35 219.29,102.8 219.29,106.61 219.1,107.06 218.65,107.25 214,107.25 213.11,107.62 212.74,108.52 212.74,114.14 213.11,115.04 214,115.41
+12V on TOP (solid shape): outline of 101 points within 231.4,39.07 239.41,49.94
+12V on TOP (solid shape): outline of 401 points within 198.59,0.97 242.55,40.19
+12V on BOTTOM: 198.59,0.97 198.59,30.25 210.32,30.25 210.32,0.97
+15V on TOP (solid shape): 225.71,46.26 221.42,46.26 221.42,48.49 225.71,48.49
+15V on TOP (solid shape): 225.71,44.03 221.42,44.03 221.42,46.26 225.71,46.26
+15V on TOP (solid shape): outline of 168 points within 220.41,41 225.82,49.31
VIN on TOP (solid shape): 230.54,14.31 226.25,14.31 226.25,16.54 230.54,16.54
VIN on TOP (solid shape): 230.54,12.08 226.25,12.08 226.25,14.31 230.54,14.31
VIN on TOP: 243.09,31.48 225.82,31.48 225.82,11.54 227.67,9.69 230.16,9.69 230.16,11.54 231.91,11.54 231.91,14.08 235.59,17.76 240.29,17.76 243.09,20.56
(no net) on TOP: 226.1,47.66 226.1,49.31 231.25,49.31 231.25,47.66
(no net) on TOP: 235.98,36.71 235.98,38.08 235.87,38.18 235.87,38.69 234.96,38.69 234.96,36.71
(no net) on TOP: 223.61,42.93 223.61,41.11 228.23,41.11 228.23,42.66 227.95,42.93
(no net) on TOP: 210.17,40.01 210.17,36.47 208.05,36.47 208.05,35.98 210.17,35.98 210.17,35 213.37,35 213.37,39.2 215.4,39.2 215.4,40.01
(no net) on TOP: 225.82,43.42 223.28,43.42 223.28,41 220.41,41 220.41,49.31 225.82,49.31
(no net) on TOP: 234.96,40.7 234.96,40.39 237.88,40.39 237.88,39.07 239.41,39.07 239.41,49.94 233.69,49.94 233.69,49.31 231.4,49.31 231.4,47.66 235.59,47.66 236.61,46.64 236.61,40.7
(no net) on TOP: 228.61,39.48 230.03,39.48 230.13,39.38 231.4,39.38 231.4,39.68 230.39,39.68 229.58,40.5 228.61,40.5
(no net) on TOP: 231.4,38.9 230.29,38.9 229.6,38.21 228.56,38.21 228.56,39.23 230.06,39.23 230.08,39.2 231.4,39.2
(no net) on TOP: 210.37,48.68 210.37,45.14 208.26,45.14 208.26,44.65 210.37,44.65 210.37,43.67 213.57,43.67 213.57,47.87 215.61,47.87 215.61,48.68
(no net) on TOP: 236.43,40.88 234.83,40.88 234.83,42.45 231.51,42.45 231.51,40.88 230.34,40.88 230.34,47.53 235.34,47.53 236.43,46.44
(no net) on TOP: 221.57,17.23 221.57,10.6 220.2,9.23 215.35,9.23 215.35,17.23
(no net) on TOP: 225.89,12.91 224.37,12.91 224.37,11.39 221.7,11.39 221.7,15.71 223.1,15.71 223.1,17.1 225.89,17.1
(no net) on TOP: 229.98,41.11 228.46,41.11 228.46,42.83 227.87,43.42 226.1,43.42 226.1,47.48 229.98,47.48
(no net) on TOP: 234.73,42.35 234.73,34.68 238.01,34.68 238.01,37.6 239.79,37.6 239.79,34.25 239.43,33.89 231.63,33.89 231.63,36.94 225.33,36.94 225.33,39.2 226.63,39.2 226.63,40.52 228.33,40.52 228.33,37.93 229.73,37.93 230.49,38.69 231.53,38.69 231.63,38.79 231.63,42.35
(no net) on TOP: 239.63,42.35 239.63,40.42 242.38,40.42 242.38,42.35
(no net) on TOP: 220.49,5.46 220.49,0.97 198.59,0.97 198.59,30.66 199.82,30.66 200.07,30.9 200.07,33.13 210.77,33.13 211.18,33.54 239.74,33.54 240.17,33.97 240.17,39.07 239.25,39.07 239.25,40.19 242.55,40.19 242.55,31.94 212.86,31.94 210.32,29.4 210.32,21.69 214.78,17.23 214.78,5.46
(no net) on GND1: 234.73,38.24 234.73,40.8 239.33,40.8 239.71,40.42 242.38,40.42 242.38,42.35 228.64,42.35 228.05,42.93 226.68,42.93 226.68,40.8 231.63,40.8 231.63,38.24
0 on TOP (solid shape): 242.38,40.42 239.63,40.42 239.63,42.35 242.38,42.35
0 on TOP (solid shape): 228.23,42.66 228.23,41.11 223.61,41.11 223.61,42.93 227.95,42.93
0 on TOP (solid shape): 215.4,39.2 213.37,39.2 213.37,35 210.17,35 210.17,35.98 208.05,35.98 208.05,36.35 208.17,36.47 210.17,36.47 210.17,37.64 210.18,37.66 210.21,37.73 210.22,37.81 210.22,38.64 210.21,38.72 210.18,38.79 210.17,38.81 210.17,40.01 215.4,40.01
0 on TOP (solid shape): 215.61,47.87 213.57,47.87 213.57,43.67 210.37,43.67 210.37,44.65 208.26,44.65 208.26,45.02 208.37,45.14 210.37,45.14 210.37,46.31 210.38,46.32 210.41,46.4 210.42,46.47 210.42,47.31 210.41,47.39 210.38,47.46 210.37,47.47 210.37,48.68 215.61,48.68
0 on TOP (solid shape): 234.71,40.75 234.73,40.75 234.73,36.34 234.68,36.22 234.55,36.19 234.5,36.2 234.45,36.2 233.97,35.72 234.45,35.24 234.51,35.24 234.57,35.25 234.73,35.25 234.73,34.68 238.01,34.68 238.01,37.6 239.79,37.6 239.79,34.25 239.43,33.89 231.63,33.89 231.63,36.94 225.33,36.94 225.33,39.2 226.63,39.2 226.63,40.33 226.79,40.49 228.33,40.49 228.33,37.93 229.73,37.93 230.49,38.69 231.53,38.69 231.63,38.79 231.63,42.32 234.71,42.32
0 on GND1 (solid shape): 228.64,42.35 242.38,42.35 242.38,40.42 239.71,40.42 239.33,40.8 234.73,40.8 234.73,38.24 231.63,38.24 231.63,40.8 226.68,40.8 226.68,42.93 228.05,42.93
0 on TOP: 222.77,31.63 222.77,18.52 214.26,18.52 210.78,22 210.78,29.45 212.96,31.63
0 on TOP, BOTTOM: 233.25,132.5 242.75,132.5
0 on TOP, BOTTOM: 233.25,12.5 242.75,12.5
0 on GND1: 234,144.49 240.71,141.71 243.49,135 243.49,122.33 243.06,121.27 242,120.84 206.63,120.84 205.58,120.4 205.14,119.34 205.14,81.61 205.58,80.56 206.63,80.12 242,80.12 243.06,79.68 243.49,78.63 243.49,10 240.71,3.29 234,0.51 126,0.51 124.94,0.94 124.51,2 124.51,4.5 120,9.01 115.49,4.5 115.49,2 115.06,0.94 114,0.51 20.68,0.51 19.62,0.94 19.19,2 19.19,5.15 19.46,6.52 20.24,7.69 27.35,14.8 28.52,15.58 29.9,15.86 47.16,15.86 48.21,16.29 48.65,17.35 48.65,106.43 48.54,107 48.21,107.48 40.71,114.99 40.38,115.47 40.27,116.04 40.27,129.1 39.83,130.15 38.78,130.59 29.9,130.59 28.52,130.86 27.35,131.64 20.24,138.76 19.46,139.92 19.19,141.3 19.19,143 19.62,144.06 20.68,144.49 114,144.49 115.06,144.06 115.49,143 115.49,140.5 120,135.99 124.51,140.5 124.51,143 124.94,144.06 126,144.49
1 on GND1, PWR2: 233.85,115.41 234.75,115.04 235.12,114.14 235.12,85.87 234.75,84.97 233.85,84.6 214,84.6 213.11,84.97 212.74,85.87 212.74,100.9 213.11,101.8 214,102.17 218.65,102.17 219.1,102.35 219.29,102.8 219.29,106.61 219.1,107.06 218.65,107.25 214,107.25 213.11,107.62 212.74,108.52 212.74,114.14 213.11,115.04 214,115.41
N147166 on TOP (solid shape): outline of 217 points within 221.7,11.39 225.89,17.1
N148540 on TOP (solid shape): 221.34,14.31 217.05,14.31 217.05,16.54 221.34,16.54
N148540 on TOP (solid shape): 221.34,12.08 217.05,12.08 217.05,14.31 221.34,14.31
N148540 on TOP (solid shape): outline of 180 points within 215.35,9.23 221.57,17.23
N5307958 on TOP (solid shape): 235.34,47.53 236.43,46.44 236.43,40.88 234.83,40.88 234.83,42.45 231.51,42.45 231.51,40.88 230.34,40.88 230.34,43.72 231.71,43.72 231.71,43.71 231.72,43.67 231.73,43.64 231.76,43.62 231.79,43.6 231.82,43.6 231.84,43.59 232.75,43.59 232.77,43.6 232.8,43.6 232.83,43.62 232.85,43.64 232.87,43.67 232.88,43.7 232.88,43.72 232.88,44.99 232.88,45.01 232.87,45.04 232.85,45.07 232.83,45.09 232.8,45.11 232.77,45.12 232.75,45.12 231.84,45.12 231.82,45.12 231.79,45.11 231.76,45.09 231.74,45.07 231.72,45.04 231.71,45.01 231.71,44.99 231.71,43.72 230.34,43.72 230.34,47.25 233.55,47.25 233.55,43.25 233.55,43.23 233.56,43.2 233.58,43.17 233.6,43.14 233.63,43.13 233.66,43.12 233.68,43.12 235.18,43.12 235.2,43.12 235.23,43.13 235.26,43.14 235.28,43.17 235.3,43.2 235.31,43.23 235.31,43.25 235.31,47.25 235.31,47.26 235.3,47.29 235.28,47.32 235.26,47.35 235.23,47.36 235.2,47.37 235.18,47.37 233.68,47.37 233.66,47.37 233.63,47.36 233.6,47.35 233.58,47.32 233.56,47.29 233.55,47.26 233.55,47.25 230.34,47.25 230.34,47.53
N5307974 on TOP (solid shape): outline of 149 points within 226.1,41.11 229.98,47.48
N5308194 on TOP (solid shape): 231.25,47.66 227.49,47.66 227.47,47.66 227.44,47.67 227.41,47.68 227.38,47.71 227.36,47.74 227.34,47.77 227.34,47.81 227.34,47.84 227.34,48.49 227.34,48.51 227.33,48.54 227.32,48.57 227.29,48.59 227.26,48.61 227.23,48.62 227.22,48.62 226.59,48.62 226.57,48.62 226.54,48.61 226.51,48.59 226.48,48.57 226.47,48.54 226.46,48.51 226.46,48.49 226.46,47.84 226.46,47.81 226.46,47.77 226.44,47.74 226.42,47.71 226.39,47.68 226.36,47.67 226.33,47.66 226.31,47.66 226.1,47.66 226.1,48.91 228.62,48.91 228.62,48.01 228.62,47.99 228.63,47.96 228.64,47.93 228.67,47.91 228.7,47.89 228.73,47.88 228.75,47.88 229.74,47.88 229.76,47.88 229.79,47.89 229.82,47.91 229.85,47.93 229.86,47.96 229.87,47.99 229.87,48.01 229.87,48.91 229.87,48.93 229.86,48.96 229.85,48.99 229.82,49.01 229.79,49.03 229.76,49.04 229.74,49.04 228.75,49.04 228.73,49.04 228.7,49.03 228.67,49.01 228.64,48.99 228.63,48.96 228.62,48.93 228.62,48.91 226.1,48.91 226.1,49.31 231.25,49.31
N5308444 on TOP (solid shape): 235.87,38.18 235.98,38.08 235.98,36.71 234.96,36.71 234.96,38.69 235.87,38.69
N5308650 on TOP (solid shape): 230.2,39.83 230.25,39.79 230.32,39.75 230.39,39.68 231.4,39.68 231.4,39.38 230.13,39.38 230.03,39.48 228.61,39.48 228.61,40.49 229.54,40.49
N5308734 on TOP (solid shape): 230.08,39.2 231.4,39.2 231.4,38.9 230.29,38.9 229.6,38.21 228.56,38.21 228.56,39.23 230.06,39.23

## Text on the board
User.Comments: CR_VOLTAGE-SENSE_MAPPED1_6 | CR_VOLTAGE-SENSE_MAPPED1_4 | CR_TEMPARTURE-FILTER_2 | CR_DIFFERENTIAL-DRIVER-V2_1 | CR_CURRENT-SENSOR-RECEIVER_1 | CR_TEMPARTURE-FILTER_1 | CR_RESOLVER-FILTER_2 | CR_RESOLVER-FILTER_1 | CR_TEMPERATURE-CONVERTER_1 | CR_LT3581-BOOST2_1 | CR_DIFFERENTIAL-DRIVER-V2_2 | CR_CURRENT-SENSOR-RECEIVER_2 | CR_VOLTAGE-SENSE-DCBUSS_MAPPED1_1 | CR_VOLTAGE-SENSE_MAPPED1_1 | CR_INPUT-PROTECTION_MAPPED1_1
Ref Des/Silkscreen Top: U | V | W | X | Y | Z | GD-W | GD-Z | GD-V | GD-Y | GND | VDC | VU | VV | VW | VX | VY | VZ | WH | ZH | ZL | WL | GD-U | GD-X | VH | YH | YL | VL | UH | XH | XL | UL | IZ | IU | IY | IV | IX | IW | EXPANSION | 3V3 | 5V | ENCODER | FLT | SA | CA | SB | CB | 9A | 9B | ESTOP | +5V | +3V3 | VIN | JTAG | RESOLVER-B | RESOLVER-A | CAN | XM3 Dual Inverter | Controller V1.3
XSECTION_CHART: *  SURFACE - 0 MIL | * SOLDERMASK_TOP MASK - 0.6 MIL | L1 TOP CONDUCTOR - 1.8 MIL | *  DIELECTRIC - 7.64 MIL | L2 GND1 CONDUCTOR - 1.2 MIL | *  DIELECTRIC - 14 MIL | L3 LAYER3 CONDUCTOR - 1.2 MIL | *  DIELECTRIC - 9.08 MIL | L4 PWR CONDUCTOR - 1.2 MIL | L5 PWR2 CONDUCTOR - 1.2 MIL | L6 BOTTOM CONDUCTOR - 1.8 MIL | * SOLDERMASK_BOTTOM MASK - 0.6 MIL | DESIGN CROSS SECTION CHART | ___________________________ | TOTAL THICKNESS 61.96 MIL | 1-6 | FIGURE | FINISHED_SIZE | 13.0 | 31.8898 | 35.0 | 39.0 | 40.0 | 41.0 | 42.0 | 45.0 | 55.0 | 63.0 | 67.0 | 122.0 | 130.0 | 140.0 | 150.0 | 55.1181 | 66.9291 | 129.0 | 165.3543 | DRILL CHART: TOP to BOTTOM | ALL UNITS ARE IN MILS | PLATED | NON-PLATED | QTY | 648 | 4 | 174 | 6 | 18 | 9 | 12 | 126 | 2 | 3 | 1
